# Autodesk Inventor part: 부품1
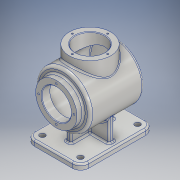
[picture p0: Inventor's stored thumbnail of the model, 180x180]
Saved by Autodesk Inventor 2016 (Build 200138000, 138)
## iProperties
Created: 2016-09
Part Number: 부품1
Material: 알루미늄 6061
Document SubType Name: Modeling
Designer: Administrator
Density: 2.7 g/cm^3
Appearance: 알루미늄 - 평지
Mass: 966.15 g
Surface Area: 1281.46 cm^2
Volume: 357.833 cm^3
Author: Administrator
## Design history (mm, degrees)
sketch "스케치1"
  geometry: L1 (-50, 0)-(60, 0); L2 (-50, 0)-(-50, 50); L3 (-50, 50)-(48.562, 50); A1 r 115 centre (-55, 0) between (60, 0) and (48.562, 50); 1 further point
  constraints: 6 end point, 2 point on circle, 1 centre point, 1 horizontal, 1 horizontal alignment, 1 perpendicular, 1 point on line, 1 vertical
  dimensions: "d0" = 110 distance of L1.start L1.end; "d1" = 115 radius of A1; "d2" = 100 diameter of L3 L1; "d3" = 50 distance of point (0, 0) L1.start
revolve "회전1" sketch "스케치1" stored, may be unused: angle "d4" = 90 deg
feature "쉘1" dims "d5" = 3
node "작업 평면1"
sketch "스케치3"
  geometry: L1 (67.5, -50)-(-67.5, -50); L2 (-67.5, -50)-(-67.5, 50); L3 (-67.5, 50)-(67.5, 50); L4 (67.5, 50)-(67.5, -50); L5 (67.5, -50)-(-67.5, 50); L6 (-67.5, -50)-(67.5, 50); 1 further point
  constraints: 12 end point, 2 midpoint, 2 parallel, 1 horizontal, 1 perpendicular
  dimensions: "d7" = 135 distance of L1.start L1.end; "d8" = 100 distance of L1.end L2.end
extrude "돌출1" join sketch "스케치3" distance "d9" = 10; taper "d10" = 0 deg
sketch "스케치4"
  geometry: L1 (-67.5, 50)-(67.5, 50) reference; L2 (67.5, 50)-(67.5, -50) reference; L3 (67.5, -50)-(-67.5, -50) reference; L4 (-67.5, -50)-(-67.5, 50) reference; L5 (67.5, 50)-(67.5, -50) reference; L6 (67.5, -50)-(-67.5, -50) reference; L7 (-67.5, -50)-(-67.5, 50) reference; L8 (-67.5, 50)-(67.5, 50) reference; L9 (-67.5, -50)-(-67.5, 50) reference; L10 (-67.5, 0)-(67.5, 0); L11 (-67.5, 50)-(67.5, 50) reference; L12 (0, 50)-(0, -50); L13 (67.5, -50)-(-67.5, -50) reference; L14 (-40, 5)-(40, 5); L15 (40, 5)-(40, -5); L16 (40, -5)-(-40, -5); L17 (-40, -5)-(-40, 5); L18 (-40, 5)-(40, -5); L19 (40, 5)-(-40, -5); 1 further point
  constraints: 16 end point, 7 midpoint, 2 parallel, 1 horizontal, 1 perpendicular
  dimensions: "d14" = 10 distance of L14.end L15.end; "d16" = 40 distance from line of L17 point (0, 0)
extrude "돌출2" join sketch "스케치4" stored distance "d17" = 10; taper "d18" = 0 deg
sketch "스케치5"
  geometry: L1 (-72, 50)-(-72, -50) reference; L2 (-82, -50)-(-72, -50) reference; L3 (-30, -40)-(-72, -40); 2 further points
  constraints: 2 end point, 1 point on line, 2 other
  dimensions: "d19" = 90 deg angle of L1 L3; "d20" = 40 vertical distance of L3.end point (0, 0)
feature "리브1" sketch "스케치5" dims "d21" = 1, "d22" = 10, "d23" = 0, "d24" = 0, "d25" = 1, "d26" = 1
node "작업 평면3"
sketch "스케치6"
  geometry: C1 r 38 at (0, 0); 1 further point
  constraints: 1 centre point, 1 coincident
  dimensions: "d28" = 76 diameter of C1
extrude "돌출3" join sketch "스케치6" stored distance "d29" = 10; taper "d30" = 0 deg
hole "구멍1" diameter "d33" = 54; stored, may be unused: countersink angle "d37" = 90 deg, drill point angle "d39" = 118 deg; dims "d31" = 10, "d32" = 10, "d34" = 6, "d35" = 4, "d36" = 2, "d38" = 8
sketch "스케치7"
  geometry: C1 r 50 at (0, 0) reference; C2 r 38 at (0, 0); 1 further point
  constraints: 1 centre point, 1 coincident
  dimensions: "d40" = 76 diameter of C2
extrude "돌출4" join sketch "스케치7" distance "d41" = 12; taper "d42" = 0 deg
hole "구멍2" diameter "d45" = 54; stored, may be unused: countersink angle "d49" = 90 deg, drill point angle "d51" = 118 deg; dims "d43" = 10, "d44" = 10, "d46" = 6, "d47" = 4, "d48" = 2, "d50" = 15
fillet "모깎기1" dims "d52" = 3
fillet "모깎기2" dims "d53" = 3
fillet "모깎기3" dims "d54" = 5
fillet "모깎기4" dims "d55" = 3
fillet "모깎기5" dims "d56" = 15
fillet "모깎기6" dims "d57" = 3
chamfer "모따기1" distance "d58" = 1; stored, may be unused: second distance "d59" = 2, angle "d60" = 45 deg
fillet "모깎기7" dims "d61" = 2
sketch "스케치8"
  geometry: L1 (67.5, 35)-(67.5, -35) reference; L2 (52.5, -50)-(-52.5, -50) reference; L3 (-67.5, -35)-(-67.5, 35) reference; L4 (-52.5, 50)-(52.5, 50) reference; C1 r 5 at (-52.5, 35); C2 r 5 at (52.5, 35); C3 r 5 at (52.5, -35); C4 r 5 at (-52.5, -35); A1 r 15 centre (52.5, 35) between (67.5, 35) and (52.5, 50) reference; A2 r 15 centre (52.5, -35) between (52.5, -50) and (67.5, -35) reference; A3 r 15 centre (-52.5, -35) between (-67.5, -35) and (-52.5, -50) reference; A4 r 15 centre (-52.5, 35) between (-52.5, 50) and (-67.5, 35) reference; A5 r 15 centre (52.5, 35) between (67.5, 35) and (52.5, 50) reference; 1 further point
  constraints: 4 centre point, 4 coincident, 3 equal radius
  dimensions: "d62" = 10 diameter of C1
extrude "돌출6" cut sketch "스케치8" stored distance "d65" = 12; taper "d66" = 0 deg
sketch "스케치9" dims "d67" = 65
  geometry: 3 further points
  constraints: 2 vertical alignment, 1 coincident, 2 other
hole "구멍3" sketch "스케치9" at (0, 32.5) diameter "d68" = 3.242; stored, may be unused: countersink angle "d72" = 90 deg, drill point angle "d74" = 118 deg; dims "d69" = 8, "d70" = 4, "d71" = 2, "d73" = 10
sketch "스케치10" dims "d78" = 65
  geometry: 3 further points
  constraints: 2 vertical alignment, 1 coincident, 2 other
hole "구멍4" sketch "스케치10" at (0, 32.5) diameter "d79" = 3.242; stored, may be unused: countersink angle "d83" = 90 deg, drill point angle "d85" = 118 deg; dims "d80" = 8, "d81" = 4, "d82" = 2, "d84" = 10
node "작업 평면4"
sketch "스케치11"
  geometry: 2 further points
  constraints: 1 coincident, 1 other
feature "엠보싱1" sketch "스케치11" dims "d0" = 110, "d1" = 115, "d2" = 100, "d3" = 50, "d90" = 0.5, "d91" = 0
node "작업 평면5"
node "솔리드1"
mirror "대칭1"
pattern_circular "원형 패턴1" dims angle "d76" = 360 deg
pattern_circular "원형 패턴2" dims angle "d87" = 360 deg
node "투영된 루프1"
node "작업 평면2"
node "투영된 루프2"
node "절단 모서리 투영1"
other parameters: "d6" = -82, "d27" = -147, "d89" = 98.425, "d92" = -109.5375
